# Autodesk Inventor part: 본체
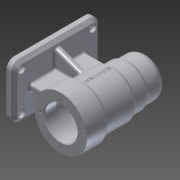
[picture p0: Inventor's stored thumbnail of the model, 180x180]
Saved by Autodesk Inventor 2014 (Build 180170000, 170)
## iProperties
Created: 2016-06
Part Number: 본체
Material: Aluminum 6061
Document SubType Name: Modeling
Designer: 601-
Density: 2.71 g/cm^3
Appearance: Aluminum - Flat
Mass: 672.182 g
Surface Area: 647.071 cm^2
Volume: 248.038 cm^3
Author: 601-
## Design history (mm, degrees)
sketch "Sketch1"
  geometry: 1 further point
sketch "Sketch2"
  geometry: L1 (-56, 35)-(56, 35); L2 (56, 35)-(56, -35); L3 (56, -35)-(-56, -35); L4 (-56, -35)-(-56, 35); L5 (56, -35)-(-56, 35); 2 further points
  constraints: 10 end point, 2 parallel, 1 coincident, 1 horizontal, 1 midpoint, 1 perpendicular
  dimensions: "d0" = 112 distance of L1.start L1.end; "d1" = 70 distance of L1.end L2.end
extrude "Extrusion1" new body sketch "Sketch2" distance "d2" = 10; taper "d3" = 0 deg
sketch "Sketch3"
  geometry: L1 (0, 70)-(0, 0) reference; C1 r 34 at (70, 35); 2 further points
  constraints: 1 centre point, 1 horizontal alignment, 1 midpoint
  dimensions: "d4" = 68 diameter of C1; "d5" = 70 distance of C1.centre point (0, 35)
extrude "Extrusion2" join sketch "Sketch3" distance "d6" = 28; taper "d7" = 0 deg
sketch "Sketch5"
  geometry: C1 r 34 at (0, 0) reference; C2 r 30 at (0, 0); 1 further point
  constraints: 1 centre point, 1 coincident
  dimensions: "d8" = 60 diameter of C2
extrude "Extrusion3" join sketch "Sketch5" distance "d9" = 39; taper "d10" = 0 deg
sketch "Sketch6"
  geometry: C1 r 30 at (0, 0) reference; C2 r 27 at (0, 0); 1 further point
  constraints: 1 centre point, 1 coincident
  dimensions: "d11" = 54 diameter of C2
extrude "Extrusion4" join sketch "Sketch6" distance "d12" = 20; taper "d13" = 0 deg
sketch "Sketch7"
  geometry: C1 r 27 at (0, 0) reference; C2 r 25 at (0, 0); 1 further point
  constraints: 1 centre point, 1 coincident
  dimensions: "d14" = 50 diameter of C2
extrude "Extrusion5" join sketch "Sketch7" distance "d15" = 25; taper "d16" = 0 deg
workplane "Work Plane2"
sketch "Sketch9"
  geometry: L1 (34, -28)-(-34, -28) reference; 3 further points
  constraints: 1 midpoint, 1 vertical alignment, 1 other
  dimensions: "d17" = 48 distance from line of L1 point (0, 20)
emboss "Emboss1" sketch "Sketch9" dims "d18" = 0.5, "d19" = 0
sketch "Sketch10"
  geometry: L1 (4, 36)-(-4, 36); L2 (-4, 36)-(-4, -36); L3 (-4, -36)-(4, -36); L4 (4, -36)-(4, 36); L5 (-4, -36)-(4, 36); L6 (25, 56)-(-25, 56) reference; 2 further points
  constraints: 10 end point, 2 parallel, 1 coincident, 1 horizontal, 1 midpoint, 1 perpendicular
  dimensions: "d21" = 20 distance between parallel lines of L6 L1; "d22" = 8 distance of L1.start L1.end
extrude "Extrusion6" join sketch "Sketch10" stored distance "d23" = 25; taper "d24" = 0 deg
sketch "Sketch11"
  geometry: L1 (-10, 4)-(-45.322, 4) reference; L2 (-10, -35)-(-10, 35) reference; L3 (-44.32, 15.509)-(-10, 28); L4 (0, 35)-(-10, 35) reference; A1 r 30 centre (-70, 0) between (-40.268, 4) and (-40.268, -4) reference; 1 further point
  constraints: 2 end point, 1 point on circle, 1 point on line
  dimensions: "d25" = 110 deg angle of L2 L3; "d26" = 7 distance from line of L4 L3.end
feature "Rib1" sketch "Sketch11" dims "d27" = 1, "d28" = 8, "d29" = 0, "d30" = 0, "d31" = 1, "d32" = 1
mirror "Mirror1"
sketch "Sketch12"
  geometry: C1 r 34 at (0, 0) reference; C2 r 21 at (0, 0); 1 further point
  constraints: 1 centre point, 1 coincident
  dimensions: "d33" = 42 diameter of C2
extrude "Extrusion7" cut sketch "Sketch12" distance "d34" = 15; taper "d35" = 0 deg
sketch "Sketch13"
  geometry: C1 r 21 at (0, 0) reference; C2 r 24 at (0, 0); 1 further point
  constraints: 1 centre point, 1 coincident
  dimensions: "d36" = 48 diameter of C2
extrude "Extrusion8" cut sketch "Sketch13" distance "d37" = 54; taper "d38" = 0 deg
sketch "Sketch14"
  geometry: C1 r 24 at (0, 0) reference; C2 r 21 at (0, 0); 1 further point
  constraints: 1 centre point, 1 coincident
  dimensions: "d39" = 42 diameter of C2
extrude "Extrusion9" cut sketch "Sketch14" distance "d40" = 12; taper "d41" = 0 deg
sketch "Sketch15"
  geometry: C1 r 21 at (0, 0) reference; C2 r 17.5 at (0, 0); 1 further point
  constraints: 1 centre point, 1 coincident
  dimensions: "d42" = 35 diameter of C2
extrude "Extrusion10" cut sketch "Sketch15" distance "d43" = 18; taper "d44" = 0 deg
sketch "Sketch16"
  geometry: C1 r 17.5 at (0, 0) reference; C2 r 16 at (0, 0); 1 further point
  constraints: 1 centre point, 1 coincident
  dimensions: "d45" = 32 diameter of C2
extrude "Extrusion11" cut sketch "Sketch16" distance "d46" = 4; taper "d47" = 0 deg
sketch "Sketch17"
  geometry: C1 r 16 at (0, 0) reference; C2 r 10.5 at (0, 0); 1 further point
  constraints: 1 centre point, 1 coincident
  dimensions: "d48" = 21 diameter of C2
extrude "Extrusion12" cut sketch "Sketch17" distance "d49" = 3; taper "d50" = 0 deg
sketch "Sketch18" dims "d51" = 52
  geometry: L1 (0, 0)-(26, 0); C1 r 21 at (0, 0) reference; C2 r 34 at (0, 0) reference; 2 further points
  constraints: 2 coincident, 2 end point, 1 horizontal, 1 horizontal alignment, 2 other
hole "Hole1" sketch "Sketch18" at (26, 0) diameter "d52" = 3.242; stored, may be unused: countersink angle "d56" = 90 deg, drill point angle "d58" = 118 deg; dims "d53" = 8, "d54" = 4, "d55" = 2, "d57" = 11
pattern_circular "Circular Pattern1" dims angle "d60" = 360 deg
fillet "Fillet1" dims "d62" = 0.3
fillet "Fillet2" dims "d63" = 3
fillet "Fillet3" dims "d64" = 10
sketch "Sketch19"
  geometry: L1 (-28, 4)-(-4, 4) reference; L2 (-4, 4)-(-4, 36) reference; L3 (-4, 36)-(4, 36) reference; L4 (4, 36)-(4, 4) reference; L5 (4, 4)-(28, 4) reference; L6 (28, 4)-(28, -4) reference; L7 (28, -4)-(4, -4) reference; L8 (4, -4)-(4, -36) reference; L9 (4, -36)-(-4, -36) reference; L10 (-4, -36)-(-4, -4) reference; L11 (-4, -4)-(-28, -4) reference; L12 (-28, -4)-(-28, 4) reference; 5 further points
hole "Hole2" sketch "Sketch19" at (-25, -46), (25, -46), (25, 46), (-25, 46) diameter "d66" = 5; stored, may be unused: countersink angle "d70" = 90 deg, drill point angle "d72" = 118 deg; dims "d67" = 8, "d68" = 9, "d69" = 4, "d71" = 11
chamfer "Chamfer1" distance "d73" = 4; stored, may be unused: second distance "d74" = 2, angle "d75" = 45 deg
fillet "Fillet5" dims "d76" = 3
fillet "Fillet6" dims "d77" = 3
fillet "Fillet7" dims "d78" = 10
fillet "Fillet8" dims "d79" = 3
fillet "Fillet9" dims "d80" = 3
fillet "Fillet17" dims "d88" = 3
fillet "Fillet18" dims "d89" = 3
fillet "Fillet19" dims "d90" = 3
fillet "Fillet20" dims "d91" = 3
chamfer "Chamfer2" distance "d92" = 1; stored, may be unused: second distance "d93" = 2, angle "d94" = 45 deg
body "Solid1"
node "Projected Loop1"
node "Projected Loop2"
node "Projected Loop3"
node "Projected Loop4"
node "Projected Loop5"
node "Projected Loop6"
node "Projected Loop7"
node "Projected Loop8"
node "Projected Loop9"
node "Projected Loop10"
node "Projected Loop11"
